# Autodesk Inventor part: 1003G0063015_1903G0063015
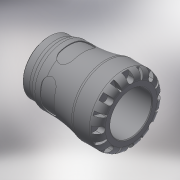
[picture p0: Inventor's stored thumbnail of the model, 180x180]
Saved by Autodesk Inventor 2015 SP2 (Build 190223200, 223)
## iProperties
Created: 2016-12
Part Number: 1003G0063015_1903G0063015
Material: Generic
Description: PLASSON FEMALE ADAPTOR 63x1 1/2" SERIES 1
Document SubType Name: Modeling
Designer: KIM
Mass: 500.169 g
Surface Area: 719.48 cm^2
Volume: 500.169 cm^3
Density: 1 g/cm^3
Appearance: Default
Author: KIM
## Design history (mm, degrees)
derived "1003G.ipt"
feature "Solid1::1003G.ipt"
tag "TaggingFeature1"
body "Solid1"
other parameters: "d0" = 125, "d1" = 37.8, "d2" = 63, "d3" = 78.75, "d4" = 103, "d8" = 87.55, "d13" = 9.7, "d14" = 9.7, "d15" = 0, "d17" = 360 deg, "d19" = 8 deg, "d20" = 1.26, "d21" = 1.26, "d22" = 8 deg, "d24" = 0, "d26" = 360 deg, "d32" = 10.3, "d33" = 10.3, "d39" = 1.34535, "d42" = 44.845, "d43" = 80.34, "d46" = 5.25, "d47" = 19, "d48" = 42.60275, "d50" = 5.28, "d51" = 1.03, "d54" = 22.05, "d55" = 13.86, "d57" = 19.012, "d58" = 0, "d68" = 360 deg, "d72" = 1.26, "d74" = 0, "d76" = 18.7425, "d_" = 63, "E_" = 103, "H_" = 125, "G_" = 44.845, "l_2" = 19, "d9" = 12.125, "d11" = 103, "d12" = 78.75, "d49" = 16
